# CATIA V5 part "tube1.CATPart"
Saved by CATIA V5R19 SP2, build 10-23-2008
Part number: tube1
Bounding box of the stored display mesh (mm): x -29.961 to 29.961, y -29.961 to 772.5, z -32.4 to 27.6
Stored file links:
  M:\EU_thinkMotion\IAO_2010\iao\IAO_MMS_Groupe2\IAO_MMS_Groupe2\mayache\mayache\Pièces\tube1.CATPart
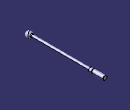
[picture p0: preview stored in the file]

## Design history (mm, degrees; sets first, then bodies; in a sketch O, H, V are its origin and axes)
Parameters
  rayboule = 30 mm
  raytubebase = 12 mm
  longbase = 600 mm
  raypist = 20 mm
  longpist = 150 mm
Body1 (main body)
  Sketch1 on zx-plane, origin (0, 0, 0), H (-1, 0, 0), V (0, 0, 1)
    line L1 (0, 27.6) -> (0, -32.4)
    point P1 (0, 27.6)
    arc A1 centre (0, -2.4) radius 30 from (0, 27.6) to (0, -32.4) ccw
    radius A1 = 30 {= rayboule}
    distance O P1 = 27.6
    length L1 = 60 {= rayboule *2}
    coincidence: P1 V
    vertical: L1 V
  Shaft1: profile Sketch1, axis Sketch1.L1, angle 360
  Plane1: type Offset, RefPlane zx-plane, Offset 22.5 {= rayboule -(rayboule /4)}
  Body2
    Sketch2 on Plane1, origin (0, 22.5, 0), H (-1, 0, 0), V (0, 0, 1)
      circle A1 centre (0, 0) radius 12
      point P1 (12, 0)
      radius A1 = 12 {= raytubebase}
      coincidence: A1 P1, P1 H
    Pad1: profile Sketch2, direction (0, 1, 0), length 600 {= longbase}
  Assemble1: tool Body2
  Fillet1: radius 10, on edge [face of Shaft1 from Sketch1.A1 | face of Pad1 from Sketch2.A1]
  Body3
    Sketch3 on end face of Pad1, origin (0, 622.5, 0), H (-1, 0, 0), V (0, 0, 1)
      circle A1 centre (0, 0) radius 20
      reference projected circle E1 centre (0, 0) radius 12 from edge [face of Pad1 from Sketch2.A1 | end face of Pad1]
      radius A1 = 20 {= raypist}
      concentricity: A1 E1
    Pad2: profile Sketch3, direction (0, 1, 0), length 150 {= longpist}
  Assemble2: tool Body3
  Fillet2: radius 5, on edge [face of Pad1 from Sketch2.A1 | start face of Pad2]
  Chamfer1: length 2, angle 45, on edge [face of Pad2 from Sketch3.A1 | end face of Pad2]
  Body4
    Sketch4 on xy-plane, origin (0, 0, 0), H (1, 0, 0), V (0, 1, 0)
      line L1 (16.6667, 656) -> (36.6667, 656)
      line L2 (36.6667, 656) -> (36.6667, 650)
      line L3 (36.6667, 650) -> (16.6667, 650)
      line L4 (16.6667, 650) -> (16.6667, 656)
      point P4 (16.6667, 650)
      reference projected line E1 through (0, 0) direction (0, 1) from axis of face of Pad2 from Sketch3.A1
      axis line L5 (0, 720) -> (0, 480)
      point P5 (0, 720)
      distance L4 E1 = 16.6667 {= raypist -(raypist /6)}
      length L4 = 6 {= longpist /25}
      distance P4 H = 650
      horizontal: L1 H, L3 H
      vertical: L2 V, L4 V, L5 V
      coincidence: P5 V
    Shaft2: profile Sketch4, axis Sketch4.L5, angle 360
  Remove1: tool Body4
